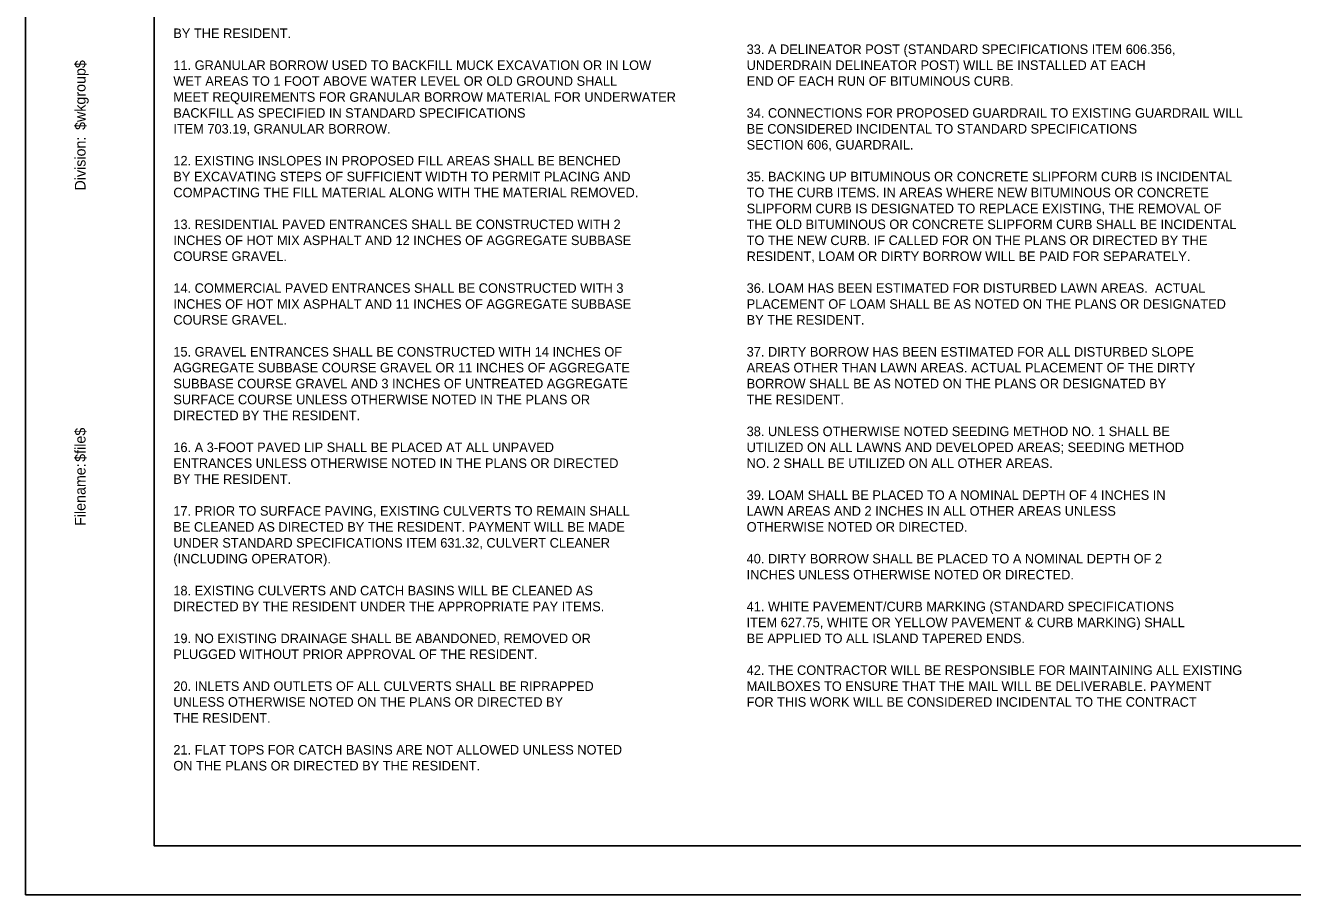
# Model space of a CAD drawing. Extents: x -0.13 to 2.72, y -0.05 to 1.78.
# Drawn here: x -0.135 to 1.191, y -0.051 to 0.859 of the extents above; entities that cross this region are included whole.
import ezdxf

# ---------------------------------------------------------------- set-up
doc = ezdxf.new("R2010")
doc.units = 0
for name, color, linetype in [('BORDER', 7, 'Continuous'), ('DIMENSIONS', 7, 'Continuous'), ('PLOT BOUNDARY', 7, 'Continuous')]:
    doc.layers.add(name, color=color, linetype=linetype)

msp = doc.modelspace()

# ---------------------------------------------------------------- linework, layer by layer
at = {"layer": 'BORDER'}
msp.add_lwpolyline([(0, 1.75), (2.6667, 1.75), (2.6667, 0), (0, 0)], close=True, dxfattribs=at)
at = {"layer": 'PLOT BOUNDARY'}
msp.add_lwpolyline([(-0.1349, -0.051), (2.6984, -0.051), (2.6984, 1.7823), (-0.1349, 1.7823)], close=True, dxfattribs=at)

# ---------------------------------------------------------------- texts
at = {"layer": 'BORDER'}
for s, p in [('$wkgroup$', (-0.0719, 0.7495)), ('Division:', (-0.0719, 0.6861)), ('$file$', (-0.0719, 0.4021)), ('Filename:', (-0.0719, 0.335))]:
    msp.add_text(s, height=0.01116, rotation=90, dxfattribs=at).set_placement(p)
at = {"layer": 'DIMENSIONS'}
for s, p in [('BY THE RESIDENT.', (0.02, 0.8457)), ('33. A DELINEATOR POST (STANDARD SPECIFICATIONS ITEM 606.356, ', (0.62, 0.829)), ('11. GRANULAR BORROW USED TO BACKFILL MUCK EXCAVATION OR IN LOW ', (0.02, 0.8123)), ('UNDERDRAIN DELINEATOR POST) WILL BE INSTALLED AT EACH ', (0.62, 0.8123)), ('WET AREAS TO 1 FOOT ABOVE WATER LEVEL OR OLD GROUND SHALL ', (0.02, 0.7957)), ('END OF EACH RUN OF BITUMINOUS CURB.   ', (0.62, 0.7957)), ('MEET REQUIREMENTS FOR GRANULAR BORROW MATERIAL FOR UNDERWATER', (0.02, 0.779)), ('BACKFILL AS SPECIFIED IN STANDARD SPECIFICATIONS ', (0.02, 0.7623)), ('34. CONNECTIONS FOR PROPOSED GUARDRAIL TO EXISTING GUARDRAIL WILL', (0.62, 0.7623)), ('ITEM 703.19, GRANULAR BORROW.', (0.02, 0.7457)), ('BE CONSIDERED INCIDENTAL TO STANDARD SPECIFICATIONS', (0.62, 0.7457)), ('SECTION 606, GUARDRAIL.', (0.62, 0.729)), ('12. EXISTING INSLOPES IN PROPOSED FILL AREAS SHALL BE BENCHED ', (0.02, 0.7123)), ('BY EXCAVATING STEPS OF SUFFICIENT WIDTH TO PERMIT PLACING AND ', (0.02, 0.6957)), ('35. BACKING UP BITUMINOUS OR CONCRETE SLIPFORM CURB IS INCIDENTAL ', (0.62, 0.6957)), ('COMPACTING THE FILL MATERIAL ALONG WITH THE MATERIAL REMOVED.', (0.02, 0.679)), ('TO THE CURB ITEMS. IN AREAS WHERE NEW BITUMINOUS OR CONCRETE ', (0.62, 0.679)), ('SLIPFORM CURB IS DESIGNATED TO REPLACE EXISTING, THE REMOVAL OF ', (0.62, 0.6623)), ('13. RESIDENTIAL PAVED ENTRANCES SHALL BE CONSTRUCTED WITH 2 ', (0.02, 0.6457)), ('THE OLD BITUMINOUS OR CONCRETE SLIPFORM CURB SHALL BE INCIDENTAL ', (0.62, 0.6457)), ('INCHES OF HOT MIX ASPHALT AND 12 INCHES OF AGGREGATE SUBBASE ', (0.02, 0.629)), ('TO THE NEW CURB. IF CALLED FOR ON THE PLANS OR DIRECTED BY THE ', (0.62, 0.629)), ('COURSE GRAVEL.', (0.02, 0.6123)), ('RESIDENT, LOAM OR DIRTY BORROW WILL BE PAID FOR SEPARATELY.', (0.62, 0.6123)), ('14. COMMERCIAL PAVED ENTRANCES SHALL BE CONSTRUCTED WITH 3 ', (0.02, 0.579)), ('36. LOAM HAS BEEN ESTIMATED FOR DISTURBED LAWN AREAS.  ACTUAL', (0.62, 0.579)), ('INCHES OF HOT MIX ASPHALT AND 11 INCHES OF AGGREGATE SUBBASE ', (0.02, 0.5623)), ('PLACEMENT OF LOAM SHALL BE AS NOTED ON THE PLANS OR DESIGNATED', (0.62, 0.5623)), ('COURSE GRAVEL.', (0.02, 0.5457)), ('BY THE RESIDENT.', (0.62, 0.5457)), ('15. GRAVEL ENTRANCES SHALL BE CONSTRUCTED WITH 14 INCHES OF ', (0.02, 0.5123)), ('37. DIRTY BORROW HAS BEEN ESTIMATED FOR ALL DISTURBED SLOPE ', (0.62, 0.5123)), ('AGGREGATE SUBBASE COURSE GRAVEL OR 11 INCHES OF AGGREGATE ', (0.02, 0.4957)), ('AREAS OTHER THAN LAWN AREAS. ACTUAL PLACEMENT OF THE DIRTY ', (0.62, 0.4957)), ('SUBBASE COURSE GRAVEL AND 3 INCHES OF UNTREATED AGGREGATE ', (0.02, 0.479)), ('BORROW SHALL BE AS NOTED ON THE PLANS OR DESIGNATED BY ', (0.62, 0.479)), ('SURFACE COURSE UNLESS OTHERWISE NOTED IN THE PLANS OR ', (0.02, 0.4623)), ('THE RESIDENT.', (0.62, 0.4623)), ('DIRECTED BY THE RESIDENT.', (0.02, 0.4457)), ('38. UNLESS OTHERWISE NOTED SEEDING METHOD NO. 1 SHALL BE ', (0.62, 0.429)), ('16. A 3-FOOT PAVED LIP SHALL BE PLACED AT ALL UNPAVED ', (0.02, 0.4123)), ('UTILIZED ON ALL LAWNS AND DEVELOPED AREAS; SEEDING METHOD ', (0.62, 0.4123)), ('ENTRANCES UNLESS OTHERWISE NOTED IN THE PLANS OR DIRECTED ', (0.02, 0.3957)), ('NO. 2 SHALL BE UTILIZED ON ALL OTHER AREAS.', (0.62, 0.3957)), ('BY THE RESIDENT.', (0.02, 0.379)), ('39. LOAM SHALL BE PLACED TO A NOMINAL DEPTH OF 4 INCHES IN', (0.62, 0.3623)), ('17. PRIOR TO SURFACE PAVING, EXISTING CULVERTS TO REMAIN SHALL ', (0.02, 0.3457)), ('LAWN AREAS AND 2 INCHES IN ALL OTHER AREAS UNLESS ', (0.62, 0.3457)), ('BE CLEANED AS DIRECTED BY THE RESIDENT. PAYMENT WILL BE MADE ', (0.02, 0.329)), ('OTHERWISE NOTED OR DIRECTED.', (0.62, 0.329)), ('UNDER STANDARD SPECIFICATIONS ITEM 631.32, CULVERT CLEANER ', (0.02, 0.3123)), ('(INCLUDING OPERATOR).', (0.02, 0.2957)), ('40. DIRTY BORROW SHALL BE PLACED TO A NOMINAL DEPTH OF 2 ', (0.62, 0.2957)), ('INCHES UNLESS OTHERWISE NOTED OR DIRECTED.', (0.62, 0.279)), ('18. EXISTING CULVERTS AND CATCH BASINS WILL BE CLEANED AS ', (0.02, 0.2623)), ('DIRECTED BY THE RESIDENT UNDER THE APPROPRIATE PAY ITEMS.', (0.02, 0.2457)), ('41. WHITE PAVEMENT/CURB MARKING (STANDARD SPECIFICATIONS ', (0.62, 0.2457)), ('ITEM 627.75, WHITE OR YELLOW PAVEMENT & CURB MARKING) SHALL ', (0.62, 0.229)), ('19. NO EXISTING DRAINAGE SHALL BE ABANDONED, REMOVED OR ', (0.02, 0.2123)), ('BE APPLIED TO ALL ISLAND TAPERED ENDS.', (0.62, 0.2123)), ('PLUGGED WITHOUT PRIOR APPROVAL OF THE RESIDENT.', (0.02, 0.1957)), ('42. THE CONTRACTOR WILL BE RESPONSIBLE FOR MAINTAINING ALL EXISTING ', (0.62, 0.179)), ('20. INLETS AND OUTLETS OF ALL CULVERTS SHALL BE RIPRAPPED ', (0.02, 0.1623)), ('MAILBOXES TO ENSURE THAT THE MAIL WILL BE DELIVERABLE. PAYMENT ', (0.62, 0.1623)), ('UNLESS OTHERWISE NOTED ON THE PLANS OR DIRECTED BY ', (0.02, 0.1457)), ('FOR THIS WORK WILL BE CONSIDERED INCIDENTAL TO THE CONTRACT', (0.62, 0.1457)), ('THE RESIDENT.', (0.02, 0.129)), ('21. FLAT TOPS FOR CATCH BASINS ARE NOT ALLOWED UNLESS NOTED ', (0.02, 0.0957)), ('ON THE PLANS OR DIRECTED BY THE RESIDENT.', (0.02, 0.079))]:
    msp.add_text(s, height=0.01, dxfattribs=at).set_placement(p)

doc.saveas('drawing.dxf')
